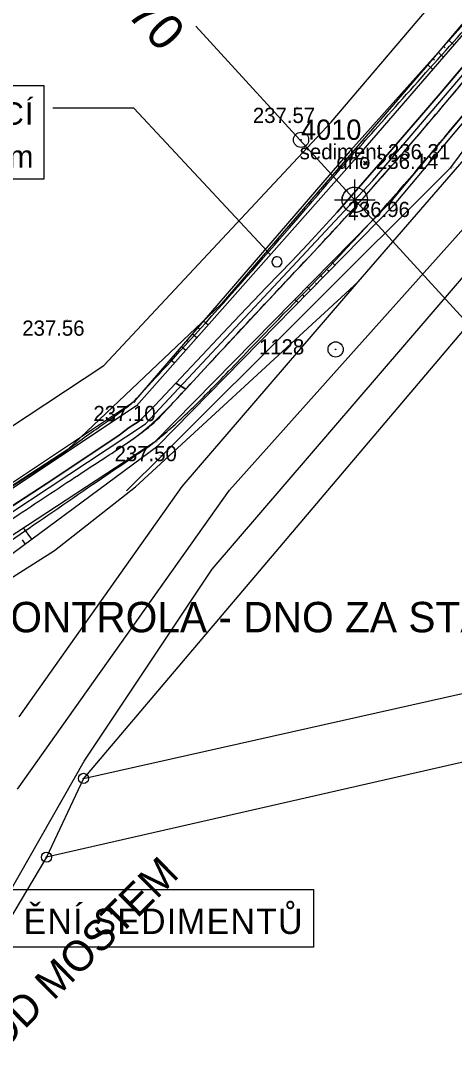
# Model space of a CAD drawing. Extents: x -555757 to -553364, y -1100723 to -1096439.
# Drawn here: x -554267.6 to -554224.9, y -1100479.7 to -1100376.4 of the extents above; entities that cross this region are included whole.
import ezdxf

# ---------------------------------------------------------------- set-up
doc = ezdxf.new("R2010")
doc.units = 0
for name, color, linetype in [('00_NÁVRH - 0.18 mm', 7, 'Continuous'), ('00_NÁVRH - 0.35 mm', 7, 'Continuous'), ('00_NÁVRH - Kóty výškové', 7, 'Continuous'), ('00_NÁVRH - Popis', 7, 'Continuous'), ('00_NÁVRH - Řezy', 7, 'Continuous'), ('01_HLADINA', 7, 'Continuous'), ('CISLO_PBPP', 7, 'Continuous'), ('Geodet. výšky - netisknuté', 7, 'Continuous'), ('HRANA$SVAHU', 7, 'Continuous'), ('HRANICE$PARCELY', 7, 'Continuous'), ('HRANICE$POROSTU', 7, 'Continuous'), ('OSA$KOLEJI', 7, 'Continuous'), ('PLOTY', 7, 'Continuous'), ('POPIS', 7, 'Continuous'), ('Poznámky', 7, 'Continuous'), ('ROZHRANI', 7, 'Continuous'), ('SLOUPY', 7, 'Continuous'), ('SLUCKOV$$C$RA', 7, 'Continuous'), ('STROMY', 7, 'Continuous'), ('VSTUP', 7, 'Continuous'), ('VYSKA_PODR_BOD', 7, 'Continuous'), ('VYSKOVE$SRAFY', 7, 'Continuous')]:
    doc.layers.add(name, color=color, linetype=linetype)

# ---------------------------------------------------------------- blocks, each defined once
blk = doc.blocks.new('POINT_DISPLAY')
blk.add_line((0, 0), (0, 0))
blk = doc.blocks.new('1$01')
at = {"layer": 'SLOUPY'}
for radius in [0.75, 0.032]:
    blk.add_circle((0, 0), radius, dxfattribs=at)
blk = doc.blocks.new('1$05')
at = {"layer": 'SLOUPY'}
for radius in [0.5, 0.032]:
    blk.add_circle((0, 0), radius, dxfattribs=at)
blk = doc.blocks.new('BOD')
at = {"layer": 'POPIS'}
for p, q in [((-0.283, -0.283), (0.283, 0.283)), ((-0.283, 0.283), (0.283, -0.283))]:
    blk.add_line(p, q, dxfattribs=at)
blk = doc.blocks.new('ZN_Výšková kóta - Půdorys')
for p, q in [((0, -2), (0, 2)), ((-2, 0), (2, 0))]:
    blk.add_line(p, q)
for points in [[(-1.25, 0), (0, 0), (0, 1.25)], [(1.25, 0), (0, 0), (0, -1.25)]]:
    blk.add_lwpolyline(points)
blk.add_circle((0, 0), 1.25)
for start, end in [(90, 180), (270, 0)]:
    blk.add_arc((0, 0), 1.25, start, end)

msp = doc.modelspace()

# ---------------------------------------------------------------- linework, layer by layer
for points in [[(-554256.48, -1100385), (-554264.48, -1100385)], [(-554243.74, -1100398.68), (-554256.48, -1100385)], [(-554243.06, -1100399.42), (-554243.74, -1100398.68)]]:
    msp.add_lwpolyline(points)
for start, end in [(132.9385, 312.9385), (312.9385, 132.9385)]:
    msp.add_arc((-554242.38, -1100400.15), 0.5, start, end)
at = {"layer": '00_NÁVRH - 0.18 mm'}
for points in [[(-554304.13, -1100440.78), (-554303.72, -1100440.51), (-554294.09, -1100434.35), (-554293.14, -1100433.68), (-554282.24, -1100425.43), (-554259.45, -1100410.38), (-554237.05, -1100386.39), (-554219.34, -1100365.55), (-554201.44, -1100345.59), (-554181.46, -1100321.95), (-554167.53, -1100306.11), (-554158.74, -1100292.84), (-554155.42, -1100286.98), (-554151.9, -1100276.1), (-554149.81, -1100266.17), (-554147.89, -1100248.91), (-554145.41, -1100226.73), (-554144.65, -1100201), (-554144.9, -1100190.12), (-554147.4, -1100181.48), (-554150.4, -1100169.83), (-554154.06, -1100160.31), (-554156.79, -1100155.91), (-554161.24, -1100148.92)], [(-554315.47, -1100482.81), (-554315.57, -1100470.17), (-554315.91, -1100465.36), (-554315.91, -1100462.93), (-554315.64, -1100462.14), (-554315.55, -1100462.06), (-554311.32, -1100457.2), (-554304.81, -1100449.72), (-554303.92, -1100449.08), (-554299.61, -1100446.26), (-554289.99, -1100440.1), (-554289.03, -1100439.44), (-554278.13, -1100431.18), (-554255.34, -1100416.13), (-554232.95, -1100392.14), (-554215.24, -1100371.3), (-554197.34, -1100351.34), (-554177.35, -1100327.7), (-554163.42, -1100311.86)]]:
    msp.add_lwpolyline(points, dxfattribs=at)
for points in [[(-554301.84, -1100444.73), (-554300.85, -1100443.94), (-554298.01, -1100441.87), (-554281.28, -1100430.6), (-554273.47, -1100425.51), (-554270.54, -1100423.6), (-554266.62, -1100421.07), (-554264.03, -1100419.37), (-554263.02, -1100418.68), (-554261.45, -1100417.5), (-554259.47, -1100416.13), (-554258.27, -1100415.28), (-554256.85, -1100414.26), (-554256.32, -1100413.75), (-554247.89, -1100404.56), (-554238.13, -1100393.33), (-554236.84, -1100391.71), (-554222.71, -1100375.93), (-554213.16, -1100365.12), (-554201.88, -1100352.5), (-554188.81, -1100337.59), (-554183.24, -1100330.95), (-554177.83, -1100324.31), (-554168.38, -1100313.81), (-554165.14, -1100310.34), (-554161.5, -1100305.37), (-554157.21, -1100299.66), (-554153.93, -1100295.13), (-554151.94, -1100292.19), (-554149.85, -1100287.66), (-554147.56, -1100282.51), (-554146.24, -1100279.73), (-554145.67, -1100278.48), (-554145.32, -1100277.04), (-554144.93, -1100274.52), (-554144.06, -1100268.79), (-554143.08, -1100262.49), (-554142.17, -1100256.52), (-554140.01, -1100242.36), (-554138.06, -1100229.56), (-554137.59, -1100222.3), (-554137.11, -1100215.05), (-554137.27, -1100209.48), (-554137.52, -1100200.88), (-554137.73, -1100193.69), (-554137.86, -1100189.31), (-554137.89, -1100188.1), (-554137.9, -1100187.6), (-554137.91, -1100187.29), (-554137.94, -1100186.71), (-554138.08, -1100186.32), (-554138.95, -1100184.13), (-554141.64, -1100177.27), (-554143.48, -1100172.65), (-554149.02, -1100158.58), (-554152.82, -1100152.33), (-554156.44, -1100146.42), (-554301.35, -1100444.33), (-554154.65, -1100149.39)], [(-554298.64, -1100448.89), (-554294.82, -1100446.56), (-554289.43, -1100442.47), (-554278.86, -1100434.83), (-554275.43, -1100432.4), (-554272, -1100429.97), (-554265.29, -1100425.33), (-554256.63, -1100419.41), (-554254.34, -1100417.95), (-554250.95, -1100414.83), (-554247.96, -1100411.8), (-554243.12, -1100406.7), (-554232.81, -1100396.12), (-554224.65, -1100386.42), (-554218.06, -1100378.48), (-554213.33, -1100372.86), (-554210.46, -1100369.69), (-554202.22, -1100360.42), (-554192.63, -1100349.43), (-554177.52, -1100331.27), (-554174.26, -1100327.3), (-554169.11, -1100321.15), (-554164.25, -1100315.58), (-554160.22, -1100310.78), (-554154.61, -1100304.16), (-554152.68, -1100301.98), (-554149.86, -1100298.79), (-554148.59, -1100297.22), (-554147.72, -1100295.2), (-554146.61, -1100292.51), (-554144.36, -1100287.06), (-554142.18, -1100281.81), (-554141.64, -1100280.41), (-554141.37, -1100279.1), (-554141.04, -1100277.69), (-554139.21, -1100268.89), (-554137.28, -1100259.96), (-554136.82, -1100257.33), (-554136.51, -1100255.85), (-554136.37, -1100255.09), (-554136.13, -1100252.77), (-554135.62, -1100248.07), (-554134.15, -1100233.99), (-554133.74, -1100230.44), (-554133.68, -1100229.74), (-554133.7, -1100229.31), (-554134.6, -1100206.07), (-554296.71, -1100447.76), (-554134.33, -1100217.7)]]:
    msp.add_open_spline(points, degree=3, dxfattribs=at)
at = {"layer": '00_NÁVRH - 0.35 mm'}
msp.add_lwpolyline([(-554289.76, -1100438.78), (-554280.27, -1100432.36), (-554277.74, -1100430.53), (-554271.29, -1100426.04), (-554264.47, -1100421.59), (-554257.95, -1100417.25), (-554256.94, -1100416.49), (-554255.97, -1100415.85), (-554254.41, -1100414.31), (-554251.35, -1100411.02), (-554246.65, -1100406.04), (-554243.4, -1100402.63), (-554240.93, -1100400.09), (-554239.33, -1100398.39), (-554236.45, -1100395.24), (-554234.36, -1100392.84), (-554231.5, -1100389.58), (-554228.52, -1100386.16), (-554226.09, -1100383.33), (-554221.34, -1100377.67)], dxfattribs=at)
msp.add_open_spline([(-554289.42, -1100440.78), (-554289.16, -1100440.58), (-554288.92, -1100440.38), (-554288.68, -1100440.19), (-554288.3, -1100439.88), (-554286.47, -1100438.33), (-554284.43, -1100436.41), (-554276.6, -1100430.73), (-554270.44, -1100426.82), (-554263.72, -1100422.29), (-554257.89, -1100418.53), (-554254.85, -1100416.45), (-554251.12, -1100412.43), (-554244.32, -1100405.05), (-554236.06, -1100396.36), (-554228.65, -1100387.95), (-554223.32, -1100381.54), (-554218.6, -1100376.08), (-554214.01, -1100370.67), (-554208.84, -1100365.01), (-554203.21, -1100358.55), (-554197.1, -1100351.87), (-554190.99, -1100344.54), (-554183.74, -1100336.01), (-554176.13, -1100327.21), (-554169.13, -1100319.05), (-554163.94, -1100313.49), (-554158.35, -1100306.5), (-554154.22, -1100300.82), (-554149.84, -1100295.85), (-554148.74, -1100293.49), (-554146.83, -1100289.75), (-554145.22, -1100285.19), (-554143.65, -1100281.32), (-554143.03, -1100279.47), (-554142.51, -1100276.5), (-554141.43, -1100271.96), (-554140.29, -1100265.07), (-554139.19, -1100259), (-554138.1, -1100251.85), (-554137.19, -1100244.92), (-554136.21, -1100237.41), (-554135.54, -1100232.51), (-554135.15, -1100229.47), (-554135.64, -1100219.84), (-554135.4, -1100209.36), (-554135.76, -1100197.79), (-554135.93, -1100193.42), (-554135.97, -1100189.84), (-554135.96, -1100187.65), (-554136.41, -1100185.68), (-554136.98, -1100184), (-554137.65, -1100181.87), (-554138.7, -1100179.2), (-554140.2, -1100174.69), (-554142.39, -1100168.62), (-554144.12, -1100163.06), (-554145.62, -1100159.04), (-554146.95, -1100156.28), (-554149.17, -1100152.8), (-554151.31, -1100149.43), (-554152.99, -1100146.74), (-554153.76, -1100145.43)], degree=3, dxfattribs=at)
at = {"layer": '00_NÁVRH - Popis'}
for points in [[(-554321.63, -1100382.78), (-554265.38, -1100382.78), (-554265.38, -1100391.99), (-554321.63, -1100391.99)], [(-554296.86, -1100462.03), (-554238.79, -1100462.03), (-554238.79, -1100467.7), (-554296.86, -1100467.7)]]:
    msp.add_lwpolyline(points, close=True, dxfattribs=at)
at = {"layer": '00_NÁVRH - Řezy'}
msp.add_line((-554223.6, -1100406.19), (-554250.38, -1100376.91), dxfattribs=at)
at = {"layer": '01_HLADINA'}
for p, q in [((-554221.34, -1100377.67), (-554226.09, -1100383.33)), ((-554226.09, -1100383.33), (-554228.52, -1100386.16)), ((-554228.52, -1100386.16), (-554231.5, -1100389.58)), ((-554231.5, -1100389.58), (-554234.36, -1100392.84)), ((-554234.36, -1100392.84), (-554236.45, -1100395.24)), ((-554236.45, -1100395.24), (-554239.33, -1100398.39)), ((-554239.33, -1100398.39), (-554240.93, -1100400.09)), ((-554240.93, -1100400.09), (-554243.4, -1100402.63)), ((-554243.4, -1100402.63), (-554246.65, -1100406.04)), ((-554246.65, -1100406.04), (-554251.35, -1100411.02)), ((-554251.35, -1100411.02), (-554252.36, -1100412.11)), ((-554252.36, -1100412.11), (-554254.41, -1100414.31)), ((-554251.38, -1100412.7), (-554252.36, -1100412.11)), ((-554252.36, -1100412.11), (-554251.38, -1100412.7)), ((-554254.41, -1100414.31), (-554255.97, -1100415.85)), ((-554256.94, -1100416.49), (-554257.95, -1100417.25)), ((-554255.97, -1100415.85), (-554256.94, -1100416.49)), ((-554257.95, -1100417.25), (-554264.47, -1100421.59)), ((-554264.47, -1100421.59), (-554271.29, -1100426.04))]:
    msp.add_line(p, q, dxfattribs=at)
for points in [[(-554237.81, -1100398.13), (-554236.66, -1100396.89), (-554233.47, -1100393.42), (-554228.65, -1100387.95), (-554223.32, -1100381.54), (-554218.6, -1100376.08), (-554214.01, -1100370.67), (-554208.84, -1100365.01), (-554203.21, -1100358.55), (-554197.8, -1100352.64), (-554194.76, -1100349.05), (-554193.55, -1100347.61)], [(-554251.38, -1100412.7), (-554249.49, -1100410.66), (-554244.99, -1100405.79), (-554240.45, -1100400.99), (-554237.81, -1100398.13)], [(-554288.68, -1100440.19), (-554288.3, -1100439.88), (-554286.47, -1100438.33), (-554284.43, -1100436.41), (-554276.6, -1100430.73), (-554270.44, -1100426.82), (-554263.72, -1100422.29), (-554257.89, -1100418.53), (-554254.85, -1100416.45), (-554253.05, -1100414.5), (-554251.86, -1100413.22), (-554251.38, -1100412.7)]]:
    msp.add_open_spline(points, degree=3, dxfattribs=at)
at = {"layer": 'HRANA$SVAHU'}
for p, q in [((-554217.38, -1100369.28), (-554235.4, -1100389.46)), ((-554217.05, -1100369.58), (-554234.75, -1100390.09)), ((-554231.17, -1100394.23), (-554213.41, -1100373)), ((-554230.81, -1100394.48), (-554213.06, -1100373.35)), ((-554235.4, -1100389.46), (-554256.51, -1100413.98)), ((-554234.75, -1100390.09), (-554256.23, -1100414.35)), ((-554254.38, -1100417.87), (-554231.17, -1100394.23)), ((-554254.14, -1100418.3), (-554230.81, -1100394.48)), ((-554256.51, -1100413.98), (-554278.71, -1100428.76)), ((-554256.23, -1100414.35), (-554278.54, -1100429.14)), ((-554287.21, -1100442.75), (-554254.14, -1100418.3)), ((-554277.58, -1100433.06), (-554254.38, -1100417.87))]:
    msp.add_line(p, q, dxfattribs=at)
at = {"layer": 'HRANICE$PARCELY'}
msp.add_line((-554261.46, -1100451.07), (-554265.1, -1100458.84), dxfattribs=at)
for points in [[(-554162.09, -1100134.23), (-554156.55, -1100150.03), (-554146.24, -1100167.08), (-554138.32, -1100193.47), (-554137.96, -1100207.15), (-554143.4, -1100261.37), (-554146.27, -1100275.63), (-554152.99, -1100291.23), (-554164.48, -1100308.32), (-554187.58, -1100335.96), (-554210.63, -1100360.69), (-554227.58, -1100380.8), (-554247.9, -1100404.32), (-554263, -1100418.66), (-554290.96, -1100436.86), (-554302.98, -1100443.3), (-554306.19, -1100445.76)], [(-554234.37, -1100402.11), (-554217.34, -1100382.44), (-554202.56, -1100365.05), (-554202.98, -1100364.72), (-554192.82, -1100351.62), (-554167, -1100326.18), (-554159.99, -1100317.82), (-554148.67, -1100300.62), (-554138.85, -1100279.5), (-554135.91, -1100262.72), (-554128.9, -1100216.98), (-554129.73, -1100211.48)], [(-554145.72, -1100316.03), (-554216.45, -1100397.94), (-554261.46, -1100451.07)], [(-554282.42, -1100440.07), (-554264.3, -1100428.61), (-554256.33, -1100422.32), (-554234.37, -1100402.11)], [(-554267.8, -1100445), (-554251.74, -1100422.3), (-554234.37, -1100402.11)], [(-554261.46, -1100451.07), (-554145.78, -1100425.12), (-554138.88, -1100424.77), (-554072.61, -1100473.21)], [(-554078.19, -1100481.08), (-554082.49, -1100474.31), (-554138.78, -1100431.67), (-554142.68, -1100430.89), (-554265.1, -1100458.84)], [(-554265.1, -1100458.84), (-554295.16, -1100509.4), (-554304.43, -1100516.2)]]:
    msp.add_lwpolyline(points, dxfattribs=at)
at = {"layer": 'PLOTY'}
for p, q in [((-554225.23, -1100390.86), (-554212.7, -1100373.7)), ((-554253.68, -1100419.2), (-554225.23, -1100390.86)), ((-554257.22, -1100422.73), (-554253.68, -1100419.2))]:
    msp.add_line(p, q, dxfattribs=at)
at = {"layer": 'SLUCKOV$$C$RA'}
for p, q in [((-554247.05, -1100422.65), (-554221.1, -1100393.62)), ((-554248.78, -1100430.46), (-554218.99, -1100395.74)), ((-554267.97, -1100452.13), (-554247.05, -1100422.65)), ((-554261.39, -1100449.36), (-554248.78, -1100430.46)), ((-554285.44, -1100491.61), (-554261.39, -1100449.36))]:
    msp.add_line(p, q, dxfattribs=at)
at = {"layer": 'VYSKOVE$SRAFY'}
for p, q in [((-554225.97, -1100378.9), (-554225.8, -1100379.05)), ((-554225.44, -1100378.3), (-554224.95, -1100378.74)), ((-554227.03, -1100380.09), (-554226.86, -1100380.24)), ((-554226.5, -1100379.49), (-554225.99, -1100379.94)), ((-554227.56, -1100380.68), (-554227.04, -1100381.15)), ((-554237.28, -1100401.08), (-554237.39, -1100400.98)), ((-554236.67, -1100400.47), (-554236.99, -1100400.16)), ((-554237.88, -1100401.7), (-554238.2, -1100401.39)), ((-554239.09, -1100402.94), (-554239.41, -1100402.62)), ((-554238.49, -1100402.32), (-554238.59, -1100402.22)), ((-554240.3, -1100404.17), (-554240.62, -1100403.86)), ((-554239.7, -1100403.56), (-554239.8, -1100403.45)), ((-554249.62, -1100405.98), (-554249.17, -1100406.37)), ((-554250.17, -1100406.61), (-554250.02, -1100406.74)), ((-554251.26, -1100407.88), (-554251.11, -1100408)), ((-554250.71, -1100407.24), (-554250.27, -1100407.62)), ((-554252.35, -1100409.14), (-554252.21, -1100409.26)), ((-554251.8, -1100408.51), (-554251.38, -1100408.87)), ((-554252.89, -1100409.78), (-554252.49, -1100410.12)), ((-554266.55, -1100427.48), (-554267.37, -1100426.37)), ((-554267.2, -1100427.95), (-554267.48, -1100427.57))]:
    msp.add_line(p, q, dxfattribs=at)

# ---------------------------------------------------------------- block references
at = {"layer": '00_NÁVRH - Kóty výškové'}
msp.add_blockref('ZN_Výšková kóta - Půdorys', (-554234.72, -1100394.04), dxfattribs=at)
at = {"layer": 'HRANICE$POROSTU'}
msp.add_blockref('1$01', (-554240.01, -1100388.12), dxfattribs=at)
at = {"layer": 'POPIS', "xscale": 0.5624965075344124, "yscale": 0.5624965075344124}
for p in [(-554233.69, -1100390.38), (-554233.61, -1100390.45)]:
    msp.add_blockref('BOD', p, dxfattribs=at)
at = {"layer": 'ROZHRANI'}
for p in [(-554240.51, -1100384.96), (-554235.4, -1100389.46), (-554234.75, -1100390.09), (-554233.69, -1100390.38), (-554233.61, -1100390.45), (-554225.23, -1100390.86), (-554231.17, -1100394.23), (-554230.81, -1100394.48), (-554263.24, -1100405.93), (-554256.51, -1100413.98), (-554256.23, -1100414.35), (-554254.38, -1100417.87), (-554254.14, -1100418.3), (-554253.68, -1100419.2)]:
    msp.add_blockref('POINT_DISPLAY', p, dxfattribs=at)
at = {"layer": 'VSTUP'}
for name, p in [('1$01', (-554236.6, -1100408.78)), ('1$05', (-554261.46, -1100451.07)), ('1$05', (-554265.1, -1100458.84))]:
    msp.add_blockref(name, p, dxfattribs=at)

# ---------------------------------------------------------------- texts
at = {"layer": '00_NÁVRH - Popis'}
for s, height, p in [('C', 2.2, (-554269.47, -1100386.63)), ('Í', 2.2, (-554267.22, -1100386.63)), ('m', 2.2, (-554268.84, -1100390.86)), ('Ě', 2.5, (-554267.36, -1100466.41)), ('N', 2.5, (-554265.01, -1100466.41)), ('Í', 2.5, (-554262.47, -1100466.41)), ('S', 2.5, (-554260.48, -1100466.41)), ('E', 2.5, (-554258.13, -1100466.41)), ('D', 2.5, (-554255.78, -1100466.41)), ('I', 2.5, (-554253.24, -1100466.41)), ('M', 2.5, (-554252.25, -1100466.41)), ('E', 2.5, (-554249.32, -1100466.41)), ('N', 2.5, (-554246.97, -1100466.41)), ('T', 2.5, (-554244.43, -1100466.41)), ('Ů', 2.5, (-554242.28, -1100466.41))]:
    msp.add_text(s, height=height, dxfattribs=at).set_placement(p)
at = {"layer": '00_NÁVRH - Řezy'}
msp.add_text('km 0,470', height=3.5, rotation=312.438, dxfattribs=at).set_placement((-554266.77, -1100365.41))
at = {"layer": 'CISLO_PBPP'}
msp.add_text('4010', height=2, dxfattribs=at).set_placement((-554240.01, -1100388.12))
at = {"layer": 'Geodet. výšky - netisknuté'}
for s, p in [('237.56', (-554235.68, -1100389.56)), ('237.19', (-554235.03, -1100390.19)), ('236.31', (-554233.97, -1100390.48)), ('236.14', (-554233.89, -1100390.55)), ('239.56', (-554225.51, -1100390.96)), ('237.55', (-554231.09, -1100394.58)), ('237.50', (-554256.79, -1100414.08)), ('237.10', (-554254.66, -1100417.97)), ('237.70', (-554253.96, -1100419.3))]:
    msp.add_text(s, height=0.1, dxfattribs=at).set_placement(p)
at = {"layer": 'OSA$KOLEJI'}
for s, p in [('344', (-554240.51, -1100384.96)), ('345', (-554235.4, -1100389.46)), ('346', (-554234.75, -1100390.09)), ('348', (-554233.69, -1100390.38)), ('347', (-554233.61, -1100390.45)), ('343', (-554225.23, -1100390.86)), ('349', (-554231.17, -1100394.23)), ('350', (-554230.81, -1100394.48)), ('337', (-554263.24, -1100405.93)), ('338', (-554256.51, -1100413.98)), ('339', (-554256.23, -1100414.35)), ('340', (-554254.38, -1100417.87)), ('341', (-554254.14, -1100418.3)), ('342', (-554253.68, -1100419.2))]:
    msp.add_text(s, height=0.1, dxfattribs=at).set_placement(p)
at = {"layer": 'POPIS'}
for s, p in [('sediment 236.31', (-554240.14, -1100390.04)), ('dno 236.14', (-554236.52, -1100390.99))]:
    msp.add_text(s, height=1.5, dxfattribs=at).set_placement(p)
at = {"layer": 'Poznámky'}
msp.add_text('KONTROLA - DNO ZA STAVIDLEM', height=3, dxfattribs=at).set_placement((-554271.34, -1100436.67))
msp.add_text('OVĚŘIT OPEVNĚNÍ POD MOSTEM', height=3, rotation=44.5788, dxfattribs=at).set_placement((-554298.4, -1100506.54))
at = {"layer": 'STROMY'}
msp.add_text('237.73', height=0.1, dxfattribs=at).set_placement((-554240.29, -1100388.17))
at = {"layer": 'VSTUP'}
msp.add_text('1128', height=1.5, dxfattribs=at).set_placement((-554244.16, -1100409.28))
at = {"layer": 'VYSKA_PODR_BOD'}
for s, p in [('237.57', (-554244.76, -1100386.46)), ('236.96', (-554235.42, -1100395.73)), ('237.56', (-554267.49, -1100407.43)), ('237.10', (-554260.48, -1100415.85)), ('237.50', (-554258.39, -1100419.8))]:
    msp.add_text(s, height=1.5, dxfattribs=at).set_placement(p)

doc.saveas('drawing.dxf')
